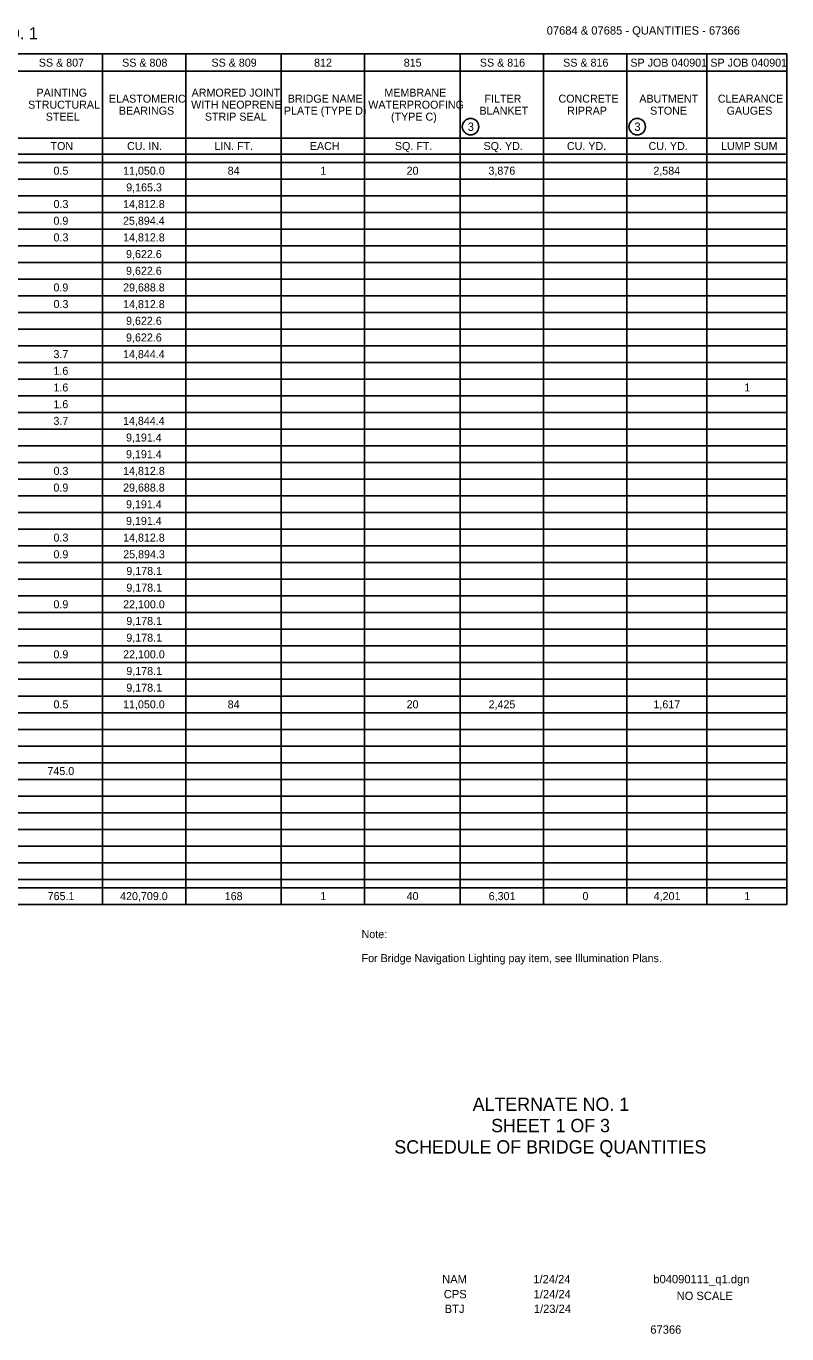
# Model space of a CAD drawing. Extents: x 0.06 to 1.38, y 0.04 to 0.85.
# Drawn here: x 0.907 to 1.382, y 0.037 to 0.854 of the extents above; entities that cross this region are included whole.
import ezdxf

# ---------------------------------------------------------------- set-up
doc = ezdxf.new("R2010")
doc.units = 0
for name, color, linetype in [('R_ROW', 7, 'Continuous'), ('R_Shade By Others', 7, 'Continuous'), ('R_Survey Control', 7, 'Continuous'), ('R_Wall', 7, 'Continuous')]:
    doc.layers.add(name, color=color, linetype=linetype)

msp = doc.modelspace()

# ---------------------------------------------------------------- linework, layer by layer
at = {"layer": 'R_Survey Control'}
for p, q in [((0.07508, 0.83695), (1.38207, 0.83695)), ((0.9543, 0.83695), (0.9543, 0.3057)), ((1.00638, 0.83695), (1.00638, 0.3057)), ((1.06595, 0.83695), (1.06595, 0.3057)), ((1.11803, 0.83695), (1.11803, 0.3057)), ((1.17793, 0.83695), (1.17793, 0.3057)), ((1.23001, 0.83695), (1.23001, 0.3057)), ((1.28209, 0.83695), (1.28209, 0.3057)), ((1.33207, 0.83695), (1.33207, 0.3057)), ((1.38207, 0.83695), (1.38207, 0.3057)), ((0.2593, 0.78445), (1.38207, 0.78445)), ((0.07508, 0.77445), (1.38207, 0.77445)), ((0.11154, 0.76924), (1.38207, 0.76924)), ((0.11154, 0.75883), (1.38207, 0.75883)), ((0.11154, 0.74841), (1.38207, 0.74841)), ((0.11154, 0.73799), (1.38207, 0.73799)), ((0.11154, 0.72758), (1.38207, 0.72758)), ((0.11154, 0.71716), (1.38207, 0.71716)), ((0.11154, 0.70674), (1.38207, 0.70674)), ((0.11154, 0.69633), (1.38207, 0.69633)), ((0.11154, 0.68591), (1.38207, 0.68591)), ((0.11154, 0.67549), (1.38207, 0.67549)), ((0.11154, 0.66508), (1.38207, 0.66508)), ((0.11154, 0.65466), (1.38207, 0.65466)), ((0.11154, 0.64424), (1.38207, 0.64424)), ((0.11154, 0.63383), (1.38207, 0.63383)), ((0.11154, 0.62341), (1.38207, 0.62341)), ((0.11154, 0.61299), (1.38207, 0.61299)), ((0.11154, 0.60258), (1.38207, 0.60258)), ((0.11154, 0.59216), (1.38207, 0.59216)), ((0.11154, 0.58174), (1.38207, 0.58174)), ((0.11154, 0.57133), (1.38207, 0.57133)), ((0.11154, 0.56091), (1.38207, 0.56091)), ((0.11154, 0.55049), (1.38207, 0.55049)), ((0.11154, 0.54008), (1.38207, 0.54008)), ((0.11154, 0.52966), (1.38207, 0.52966)), ((0.11154, 0.51924), (1.38207, 0.51924)), ((0.11154, 0.50883), (1.38207, 0.50883)), ((0.11154, 0.49841), (1.38207, 0.49841)), ((0.11154, 0.48799), (1.38207, 0.48799)), ((0.11154, 0.47758), (1.38207, 0.47758)), ((0.11154, 0.46716), (1.38207, 0.46716)), ((0.11154, 0.45674), (1.38207, 0.45674)), ((0.11154, 0.44633), (1.38207, 0.44633)), ((0.11154, 0.43591), (1.38207, 0.43591)), ((0.11154, 0.42549), (1.38207, 0.42549)), ((0.11154, 0.41508), (1.38207, 0.41508)), ((0.11154, 0.40466), (1.38207, 0.40466)), ((0.11154, 0.39424), (1.38207, 0.39424)), ((0.11154, 0.38383), (1.38207, 0.38383)), ((0.11154, 0.37341), (1.38207, 0.37341)), ((0.11154, 0.36299), (1.38207, 0.36299)), ((0.11154, 0.35258), (1.38207, 0.35258)), ((0.11154, 0.34216), (1.38207, 0.34216)), ((0.11154, 0.33174), (1.38207, 0.33174)), ((0.11154, 0.32133), (1.38207, 0.32133)), ((0.07508, 0.31612), (1.38207, 0.31612)), ((0.07508, 0.3057), (1.38207, 0.3057))]:
    msp.add_line(p, q, dxfattribs=at)
msp.add_lwpolyline([(0.2593, 0.82612), (0.30758, 0.82612), (0.41883, 0.82612), (0.46733, 0.82612), (0.509, 0.82612), (0.60403, 0.82612), (0.64048, 0.82612), (0.68476, 0.82612), (0.72903, 0.82612), (0.79673, 0.82612), (0.84248, 0.82612), (0.89457, 0.82612), (0.99353, 0.82612), (1.05082, 0.82612), (1.11332, 0.82612), (1.1813, 0.82612), (1.249, 0.82612), (1.249, 0.82612), (1.30109, 0.82612), (1.38207, 0.82612)], dxfattribs=at)
at = {"layer": 'R_Wall'}
for centre in [(1.18434, 0.79152), (1.2885, 0.79152)]:
    msp.add_circle(centre, 0.00515, dxfattribs=at)

# ---------------------------------------------------------------- texts
at = {"layer": 'R_ROW'}
msp.add_text('SCHEDULE OF BRIDGE QUANTITIES - JOB NO. 040901 - ALTERNATE NO. 1', height=0.0075, dxfattribs=at).set_placement((0.55601, 0.84612))
at = {"layer": 'R_Shade By Others'}
for s, height, p in [('07684 & 07685 - QUANTITIES - 67366', 0.0052083, (1.23194, 0.84904)), ('ALTERNATE NO. 1', 0.0083332, (1.18566, 0.17677)), ('SHEET 1 OF 3', 0.0083332, (1.1972, 0.16344)), ('SCHEDULE OF BRIDGE QUANTITIES', 0.0083332, (1.13669, 0.1501)), ('NAM', 0.005208, (1.1666, 0.06906)), ('1/24/24', 0.005208, (1.22357, 0.06906)), ('b04090111_q1.dgn', 0.0052083, (1.29862, 0.06906)), ('CPS', 0.005208, (1.1676, 0.05969)), ('1/24/24', 0.005208, (1.22378, 0.05969)), ('NO SCALE', 0.005208, (1.31316, 0.05864)), ('BTJ', 0.005208, (1.16819, 0.05052)), ('1/23/24', 0.005208, (1.22389, 0.05052)), ('67366', 0.005208, (1.29672, 0.03756))]:
    msp.add_text(s, height=height, dxfattribs=at).set_placement(p)
at = {"layer": 'R_Survey Control'}
for s, p in [('SS & 807', (0.91446, 0.82904)), ('SS & 808', (0.96655, 0.82904)), ('SS & 809', (1.02239, 0.82904)), ('812', (1.08651, 0.82904)), ('815', (1.14258, 0.82904)), ('SS & 816', (1.19016, 0.82904)), ('SS & 816', (1.24225, 0.82904)), ('SP JOB 040901', (1.28425, 0.82904)), ('SP JOB 040901', (1.33425, 0.82904)), ('PAINTING', (0.91301, 0.81029)), ('ELASTOMERIC', (0.95828, 0.80654)), ('ARMORED JOINT', (1.00997, 0.81029)), ('BRIDGE NAME', (1.07009, 0.80654)), ('MEMBRANE', (1.13047, 0.81029)), ('FILTER', (1.19306, 0.80654)), ('CONCRETE', (1.23931, 0.80654)), ('ABUTMENT', (1.28984, 0.80654)), ('CLEARANCE', (1.33894, 0.80654)), ('STRUCTURAL', (0.90772, 0.80279)), ('BEARINGS', (0.96449, 0.79904)), ('WITH NEOPRENE', (1.00965, 0.80279)), ('PLATE (TYPE D)', (1.06764, 0.79904)), ('WATERPROOFING', (1.1204, 0.80279)), ('(TYPE C)', (1.13463, 0.79529)), ('BLANKET', (1.18992, 0.79904)), ('RIPRAP', (1.24471, 0.79904)), ('STONE', (1.29661, 0.79904)), ('GAUGES', (1.34441, 0.79904)), ('STEEL', (0.91878, 0.79529)), ('STRIP SEAL', (1.01825, 0.79529)), ('TON', (0.92178, 0.77695)), ('CU. IN.', (0.96961, 0.77695)), ('LIN. FT.', (1.02424, 0.77695)), ('EACH', (1.08387, 0.77695)), ('SQ. FT.', (1.13705, 0.77695)), ('SQ. YD.', (1.19247, 0.77695)), ('CU. YD.', (1.24459, 0.77695)), ('CU. YD.', (1.29561, 0.77695)), ('LUMP SUM', (1.34093, 0.77695)), ('0.5', (0.92364, 0.76154)), ('11,050.0', (0.96714, 0.76154)), ('84', (1.0325, 0.76154)), ('1', (1.09039, 0.76154)), ('20', (1.14437, 0.76154)), ('3,876', (1.19554, 0.76154)), ('2,584', (1.29862, 0.76154)), ('9,165.3', (0.96907, 0.75112)), ('0.3', (0.92366, 0.7407)), ('14,812.8', (0.96713, 0.7407)), ('0.9', (0.92361, 0.73029)), ('25,894.4', (0.96709, 0.73029)), ('0.3', (0.92366, 0.71987)), ('14,812.8', (0.96713, 0.71987)), ('9,622.6', (0.96899, 0.70945)), ('9,622.6', (0.96899, 0.69904)), ('0.9', (0.92361, 0.68862)), ('29,688.8', (0.96713, 0.68862)), ('0.3', (0.92366, 0.6782)), ('14,812.8', (0.96713, 0.6782)), ('9,622.6', (0.96899, 0.66779)), ('9,622.6', (0.96899, 0.65737)), ('3.7', (0.92359, 0.64695)), ('14,844.4', (0.96709, 0.64695)), ('1.6', (0.92358, 0.63654)), ('1.6', (0.92358, 0.62612)), ('1', (1.35547, 0.62612)), ('1.6', (0.92358, 0.6157)), ('3.7', (0.92359, 0.60529)), ('14,844.4', (0.96709, 0.60529)), ('9,191.4', (0.96897, 0.59487)), ('9,191.4', (0.96897, 0.58445)), ('0.3', (0.92366, 0.57404)), ('14,812.8', (0.96713, 0.57404)), ('0.9', (0.92361, 0.56362)), ('29,688.8', (0.96713, 0.56362)), ('9,191.4', (0.96897, 0.5532)), ('9,191.4', (0.96897, 0.54279)), ('0.3', (0.92366, 0.53237)), ('14,812.8', (0.96713, 0.53237)), ('0.9', (0.92361, 0.52195)), ('25,894.3', (0.9672, 0.52195)), ('9,178.1', (0.96916, 0.51154)), ('9,178.1', (0.96916, 0.50112)), ('0.9', (0.92361, 0.4907)), ('22,100.0', (0.96714, 0.4907)), ('9,178.1', (0.96916, 0.48029)), ('9,178.1', (0.96916, 0.46987)), ('0.9', (0.92361, 0.45945)), ('22,100.0', (0.96714, 0.45945)), ('9,178.1', (0.96916, 0.44904)), ('9,178.1', (0.96916, 0.43862)), ('0.5', (0.92364, 0.4282)), ('11,050.0', (0.96714, 0.4282)), ('84', (1.0325, 0.4282)), ('20', (1.14437, 0.4282)), ('2,425', (1.1956, 0.4282)), ('1,617', (1.29866, 0.4282)), ('745.0', (0.91985, 0.38654)), ('765.1', (0.91999, 0.30841)), ('420,709.0', (0.96527, 0.30841)), ('168', (1.03066, 0.30841)), ('1', (1.09039, 0.30841)), ('40', (1.14437, 0.30841)), ('6,301', (1.1957, 0.30841)), ('0', (1.25431, 0.30841)), ('4,201', (1.29882, 0.30841)), ('1', (1.35547, 0.30841)), ('Note:', (1.11623, 0.28467)), ('For Bridge Navigation Lighting pay item, see Illumination Plans.', (1.11623, 0.26967))]:
    msp.add_text(s, height=0.005, dxfattribs=at).set_placement(p)
at = {"layer": 'R_Wall'}
for p in [(1.18258, 0.78892), (1.28675, 0.78892)]:
    msp.add_text('3', height=0.00521, dxfattribs=at).set_placement(p)

doc.saveas('drawing.dxf')
